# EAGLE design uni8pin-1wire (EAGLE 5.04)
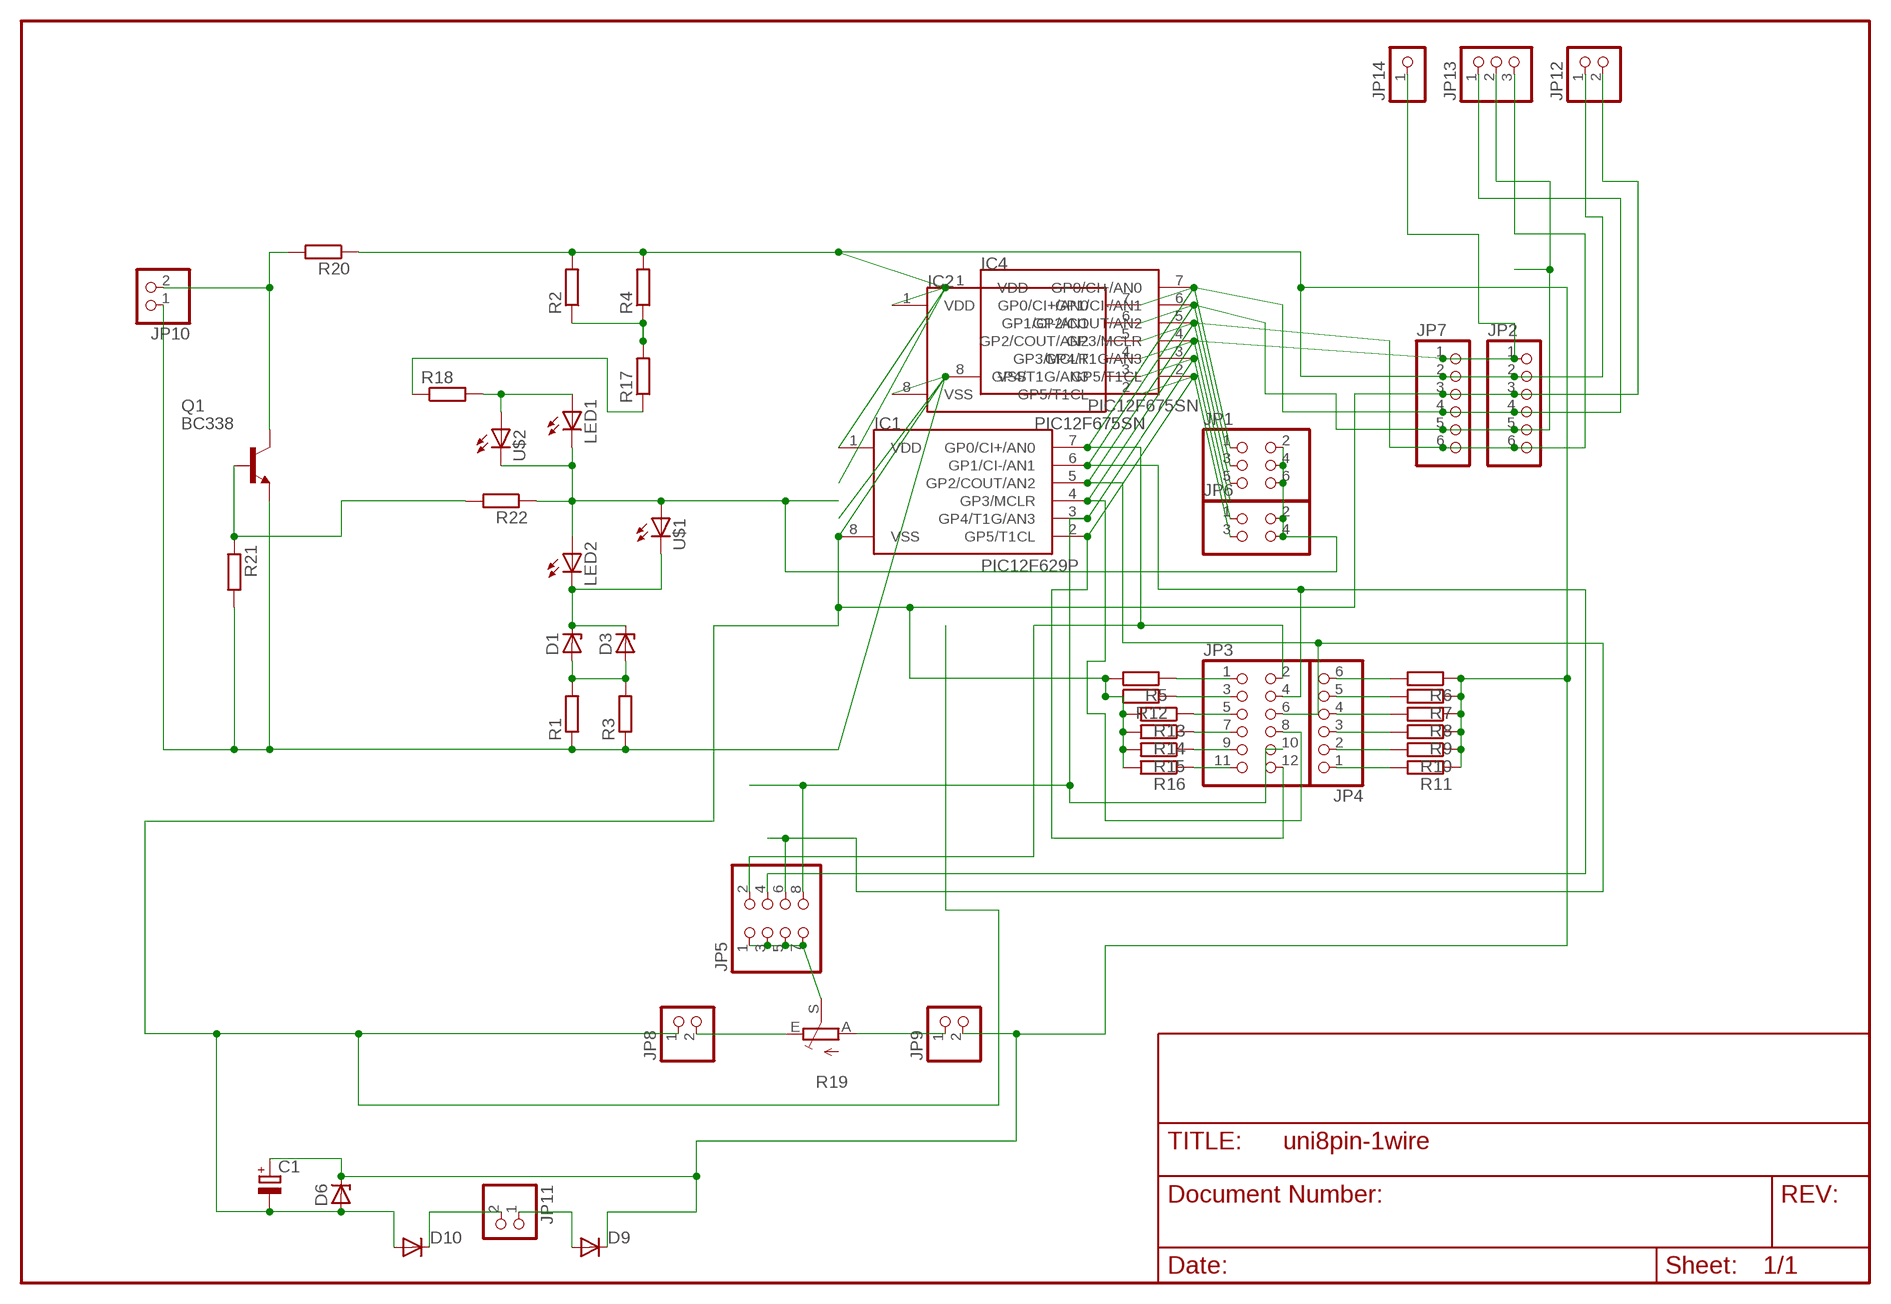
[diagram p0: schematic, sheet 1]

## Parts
C1  CPOL-EU5-13  [2,5-5-FLAT]
D1  ZENER-DIODESOT23  [SOT23]
D3  ZENER-DIODEZD-2.5  [ZDIO-2.5]
D6  ZENER-DIODEZD-2.5  [ZDIO-2.5]
D9  DIODE-D-5  [D-5]
D10  DIODE-D-5  [D-5]
IC1  PIC12F629P  [DIL8]
IC2  PIC12F675SN  [SO-08]
IC4  PIC12F675SN  [SO-08]
JP1  PINHD-2X3  [2X03]
JP2  PINHD-1X6  [1X06]
JP3  PINHD-2X6  [2X06]
JP4  PINHD-1X6  [1X06]
JP5  PINHD-2X4  [2X04]
JP6  PINHD-2X2  [2X02]
JP7  PINHD-1X6  [1X06]
JP8  PINHD-1X2  [1X02]
JP9  PINHD-1X2  [1X02]
JP10  PINHD-1X2  [1X02]
JP11  PINHD-1X2  [1X02]
JP12  PINHD-1X2  [1X02]
JP13  PINHD-1X3  [1X03]
JP14  PINHD-1X1  [1X01]
LED1  LED5MM  [LED5MM]
LED2  LED5MM  [LED5MM]
Q1  BC338  [TO92-EBC]
R1  R-EU_0204/2V  [0204V]
R2  R-EU_0204/2V  [0204V]
R3  R-EU_R1206  [R1206]
R4  R-EU_R1206  [R1206]
R5  R-EU_R1206  [R1206]
R6  R-EU_R1206  [R1206]
R7  R-EU_R1206  [R1206]
R8  R-EU_R1206  [R1206]
R9  R-EU_R1206  [R1206]
R10  R-EU_R1206  [R1206]
R11  R-EU_R1206  [R1206]
R12  R-EU_R1206  [R1206]
R13  R-EU_R1206  [R1206]
R14  R-EU_R1206  [R1206]
R15  R-EU_R1206  [R1206]
R16  R-EU_R1206  [R1206]
R17  R-EU_R0805  [R0805]
R18  R-EU_R0805  [R0805]
R19  TRIM_EU-CA6V  [CA6V]
R20  R-EU_R0805  [R0805]
R21  R-EU_R0805  [R0805]
R22  R-EU_R0805  [R0805]
U$1  LEDCHIPLED_1206  [CHIPLED_1206]
U$2  LEDCHIPLED_1206  [CHIPLED_1206]

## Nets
N$1: IC1.3(GP4/T1G/AN3) IC2.3(GP4/T1G/AN3) IC4.3(GP4/T1G/AN3) JP3.10 JP5.8 JP6.1
N$2: D1.3(C) D3.C LED2.K(C) U$1.C
N$3: D1.1(A) D3.A R1.2 R3.2
N$4: JP1.2 JP1.4 JP1.6 JP6.2 JP6.4 LED1.K(C) LED2.A R22.1 U$1.A U$2.C
N$5: JP10.2 Q1.C R20.2
N$7: R2.1 R4.1 R17.2
N$8: R17.1 R18.1
N$9: IC1.2(GP5/T1CL) IC2.2(GP5/T1CL) IC4.2(GP5/T1CL) JP3.12 JP6.3
N$10: LED1.A R18.2 U$2.A
N$11: IC1.4(GP3/MCLR) IC2.4(GP3/MCLR) IC4.4(GP3/MCLR) JP2.1 JP3.8 JP7.1 JP14.1
N$12: IC1.5(GP2/COUT/AN2) IC2.5(GP2/COUT/AN2) IC4.5(GP2/COUT/AN2) JP1.5 JP2.6 JP3.6 JP5.6 JP7.6 JP13.3
N$13: IC1.6(GP1/CI-/AN1) IC2.6(GP1/CI-/AN1) IC4.6(GP1/CI-/AN1) JP1.3 JP2.5 JP3.4 JP5.4 JP7.5 JP13.2
N$14: IC1.7(GP0/CI+/AN0) IC2.7(GP0/CI+/AN0) IC4.7(GP0/CI+/AN0) JP1.1 JP2.4 JP3.2 JP5.2 JP7.4 JP13.1
N$15: JP4.6 R6.2
N$16: JP5.1 JP5.3 JP5.5 JP5.7 R19.S
N$17: Q1.B R21.1 R22.2
N$18: JP3.1 R5.1
N$21: JP3.3 R12.1
N$22: JP3.5 R13.1
N$23: JP3.7 R14.1
N$24: JP3.9 R15.1
N$25: JP3.11 R16.1
N$26: JP4.5 R7.2
N$27: JP4.4 R8.2
N$28: JP4.3 R9.2
N$29: JP4.2 R10.2
N$30: JP4.1 R11.2
N$31: JP9.1 R19.A
N$32: JP8.2 R19.E
N$34: D10.C JP11.2
N$35: D9.A JP11.1
VDD: C1.+ D6.C D9.C IC1.1(VDD) IC2.1(VDD) IC4.1(VDD) JP2.2 JP7.2 JP9.2 JP12.1 R2.2 R4.2 R6.1 R7.1 R8.1 R9.1 R10.1 R11.1 R20.1
VSS: C1.- D6.A D10.A IC1.8(VSS) IC2.8(VSS) IC4.8(VSS) JP2.3 JP7.3 JP8.1 JP10.1 JP12.2 Q1.E R1.1 R3.1 R5.2 R12.2 R13.2 R14.2 R15.2 R16.2 R21.2

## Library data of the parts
C1 = rcl-2:CPOL-EU: POLARIZED CAPACITOR, European symbol
D1 D3 D6 = diode-1:ZENER-DIODE: Z-Diode
D9 D10 = diode-1:DIODE-: DIODE
IC1 IC2 IC4 = microchip-5:PIC12F6*: uPC nW 1k Program Flash memory 2x Timer Comparator 10b A/D converter/ 4xIN
JP1 = pinhead(2):PINHD-2X3: PIN HEADER
JP2 JP7 = pinhead:PINHD-1X6: PIN HEADER
JP3 = pinhead(2):PINHD-2X6: PIN HEADER
JP4 = pinhead(2):PINHD-1X6: PIN HEADER
JP5 = pinhead(2):PINHD-2X4: PIN HEADER
JP6 = pinhead(2):PINHD-2X2: PIN HEADER
JP8-JP11 = pinhead(2):PINHD-1X2: PIN HEADER
JP12 = pinhead:PINHD-1X2: PIN HEADER
JP13 = pinhead:PINHD-1X3: PIN HEADER
JP14 = pinhead:PINHD-1X1: PIN HEADER
LED1 LED2 = led:LED: LED
Q1 = transistor-npn:BC338*: NPN Transistor
R1-R18 R20-R22 = rcl-2:R-EU_: RESISTOR, European symbol
R19 = pot:TRIM_EU-: POTENTIOMETER
U$1 U$2 = led(2):LED: LED

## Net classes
0 default: width 0.3 mm, drill 0.6 mm, clearance 0.2 mm
1 power: width 0.4 mm, drill 0.6 mm, clearance 0.2 mm

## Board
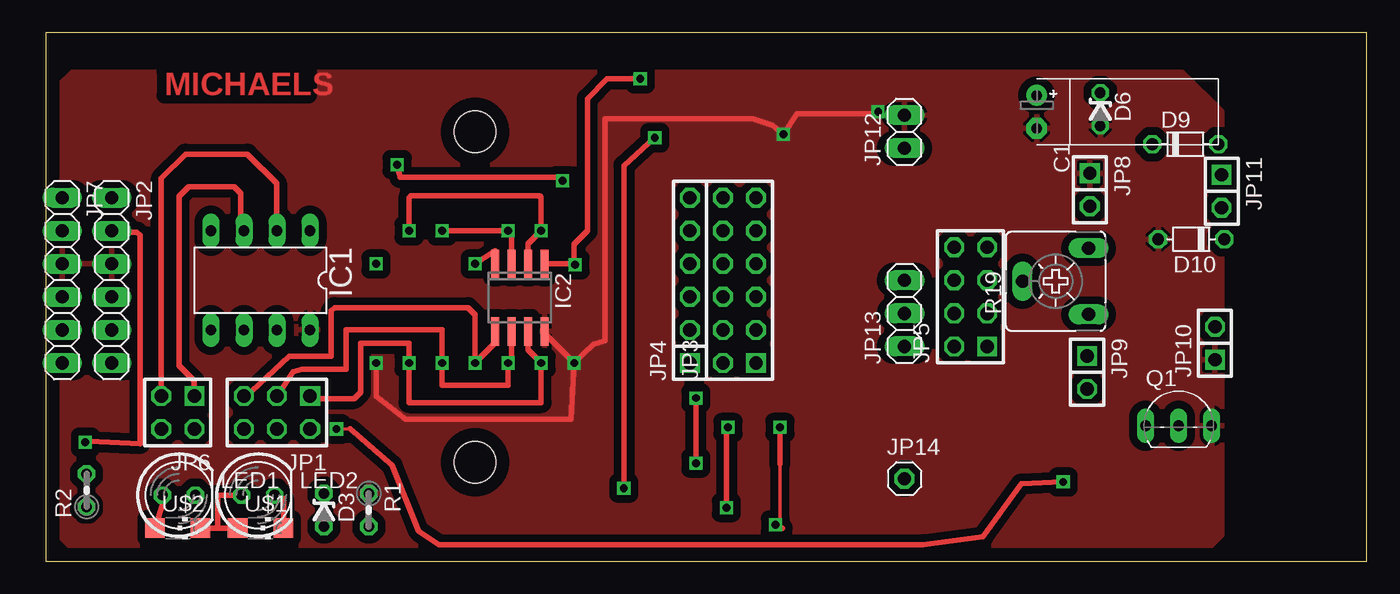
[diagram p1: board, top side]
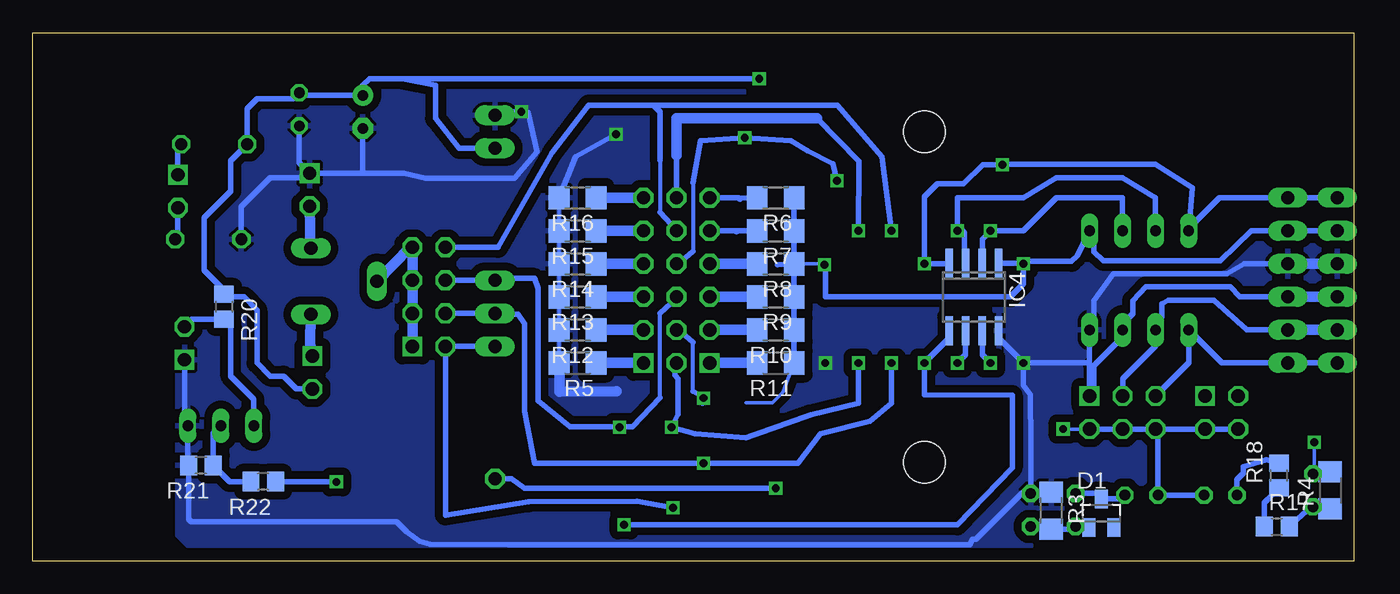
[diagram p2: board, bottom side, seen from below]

Size 101.6 x 40.64 mm. Coordinates in mm from the lower left corner, seen from the top.
Outline: 0,0 101.6,0 101.6,40.64 0,40.64 0,0
Copper layers (1*16): Top 0.035mm / dielectric 1.5mm / Bottom 0.035mm
Design rules "default": minimum track width 10mil, minimum drill 24mil, track to track 8mil, track to pad 8mil, pad to pad 8mil, via to via 8mil, smd to smd 8mil, copper to edge 40mil, drill to drill 8mil, minimum pad ring 10mil, minimum via ring 8mil, stop-mask expansion 4mil, vias tented up to drill 0mil, thermal gap 10mil
Holes 3.2 mm at 33.02,33.02 33.02,7.62

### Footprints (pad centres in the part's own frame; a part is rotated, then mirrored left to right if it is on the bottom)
2,5-5-FLAT = drill 0.813 pad 1.6 round: + -1.27,0 | drill 0.813 pad 1.6 octagon: - 1.27,0
SOT23 = smd 1 x 1.4: 1 -0.95,-1.1; 2 0.95,-1.1; 3 0,1.1
ZDIO-2.5 = drill 0.813 octagon: A 1.27,0; C -1.27,0
D-5 = drill 0.9 octagon: A 2.54,0; C -2.54,0
DIL8 = drill 0.813 long: 1 -3.81,-3.81; 2 -1.27,-3.81; 3 1.27,-3.81; 4 3.81,-3.81; 5 3.81,3.81; 6 1.27,3.81; 7 -1.27,3.81; 8 -3.81,3.81
SO-08 = smd 0.6 x 2.2: 1 -1.905,-2.6; 2 -0.635,-2.6; 3 0.635,-2.6; 4 1.905,-2.6; 5 1.905,2.6; 6 0.635,2.6; 7 -0.635,2.6; 8 -1.905,2.6
2X03 = drill 1.016 square: 1 -2.54,-1.27 | drill 1.016 octagon: 2 -2.54,1.27; 3 0,-1.27; 4 0,1.27; 5 2.54,-1.27; 6 2.54,1.27
1X06 = drill 1.016 long: 1 -6.35,0; 2 -3.81,0; 3 -1.27,0; 4 1.27,0; 5 3.81,0; 6 6.35,0
2X06 = drill 1.016 square: 1 -6.35,-1.27 | drill 1.016 octagon: 2 -6.35,1.27; 3 -3.81,-1.27; 4 -3.81,1.27; 5 -1.27,-1.27; 6 -1.27,1.27; 7 1.27,-1.27; 8 1.27,1.27; 9 3.81,-1.27; 10 3.81,1.27; 11 6.35,-1.27; 12 6.35,1.27
1X06' = drill 1.016 square: 1 -6.35,0 | drill 1.016 octagon: 2 -3.81,0; 3 -1.27,0; 4 1.27,0; 5 3.81,0; 6 6.35,0
2X04 = drill 1.016 square: 1 -3.81,-1.27 | drill 1.016 octagon: 2 -3.81,1.27; 3 -1.27,-1.27; 4 -1.27,1.27; 5 1.27,-1.27; 6 1.27,1.27; 7 3.81,-1.27; 8 3.81,1.27
2X02 = drill 1.016 square: 1 -1.27,-1.27 | drill 1.016 octagon: 2 -1.27,1.27; 3 1.27,-1.27; 4 1.27,1.27
1X02 = drill 1.016 square: 1 -1.27,0 | drill 1.016 octagon: 2 1.27,0
1X02' = drill 1.016 long: 1 -1.27,0; 2 1.27,0
1X03 = drill 1.016 long: 1 -2.54,0; 2 0,0; 3 2.54,0
1X01 = drill 1.016 octagon: 1 0,0
LED5MM = drill 0.813 octagon: A -1.27,0; K 1.27,0
TO92-EBC = drill 0.813 long: B 0,-1.27; C -2.54,-1.27; E 2.54,-1.27
0204V = drill 0.813 octagon: 1 -1.27,0; 2 1.27,0
R1206 = smd 1.6 x 1.803: 1 -1.422,0; 2 1.422,0
R0805 = smd 1.3 x 1.5: 1 -0.95,0; 2 0.95,0
CA6V = drill 1.016 long: A -2.54,-2.54; E 2.54,-2.54; S 0,2.54
CHIPLED_1206 = smd 1.5 x 1.5: A 0,-1.75; C 0,1.75

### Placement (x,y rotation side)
C1  76.2,34.54 270 top
D1  19.4,3.69 0 bottom
D3  21.39,3.94 270 top
D6  81.09,34.74 270 top
D9  87.63,32.06 0 top
D10  88.09,24.75 180 top
IC1  16.51,21.59 180 top
IC2  36.46,20.26 180 top
IC4  29.21,20.32 180 bottom
JP1  17.78,11.43 180 top
JP2  5.08,21.59 270 top
JP3  53.34,21.59 90 top
JP4  [1X06']  49.53,21.59 90 top
JP5  71.12,20.32 90 top
JP6  10.16,11.43 180 top
JP7  1.27,21.59 270 top
JP8  80.3,28.56 270 top
JP9  80.08,14.51 270 top
JP10  89.92,16.76 90 top
JP11  90.42,28.45 270 top
JP12  [1X02']  66.04,33.02 90 top
JP13  66.04,19.05 90 top
JP14  66.04,6.35 0 top
LED1  10.24,5.08 0 top
LED2  16.33,5.08 0 top
Q1  87.12,11.68 0 top
R1  24.85,3.94 270 top
R2  3.14,5.45 90 top
R3  23.27,3.89 270 bottom
R4  1.81,5.46 90 bottom
R5  59.69,15.24 180 bottom
R6  44.45,27.94 180 bottom
R7  44.45,25.4 180 bottom
R8  44.45,22.86 180 bottom
R9  44.45,20.32 180 bottom
R10  44.45,17.78 180 bottom
R11  44.45,15.24 180 bottom
R12  59.69,17.78 180 bottom
R13  59.69,20.32 180 bottom
R14  59.69,22.86 180 bottom
R15  59.69,25.4 180 bottom
R16  59.69,27.94 180 bottom
R17  5.92,2.66 0 bottom
R18  5.75,6.59 90 bottom
R19  77.66,21.52 90 top
R20  86.87,19.56 270 bottom
R21  88.65,7.37 180 bottom
R22  83.86,6.11 180 bottom
U$1  16.51,2.54 270 top
U$2  10.16,2.54 270 top

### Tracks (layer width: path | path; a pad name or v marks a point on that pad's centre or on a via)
N$1  (via drill 0.6)
  Top 0.406: JP6.1 11.43,13.86 10.25,15.04 10.25,28.04 11,28.79 14.5,28.79 15,28.29 15,25.79 14.97,25.82 IC1.3 | IC2.3 35.83,25.14 v35.56,25.4 v30.48,25.4
  Bottom 0.305: 53.34,30.83 53.34,26.83
  Bottom 0.406: JP3.10 52.07,25.44 53.34,26.83 | v35.56,25.4 36.27,31.1 39.71,35.05 53.85,35.05 | IC1.3 15.24,27.94 17.78,29.46 22.86,29.46 25.4,27.94 30.48,27.94 v30.48,25.4 30.11,25.4 29.96,25.25 29.96,23.04 IC4.3 | JP5.8 65.81,24.13 61.64,31.41 58.84,35.05 53.85,35.05 | 53.34,30.83 53.34,34.54 53.85,35.05
N$2
  Top 0.406: U$1.C 18.29,2.54 18.29,4.79 17.6,4.79 LED2.K
  Bottom 0.406: D3.C 19.82,5.21 D1.3 17.9,4.79 LED2.K
N$3
  Bottom 0.406: R1.2 23.47,2.67 R3.2 21.6,2.46 D3.A 20.43,2.67 D1.1
N$4  (via drill 0.6)
  Top 0.254: v22.35,10.16 23.4,10.17
  Top 0.406: 23.4,10.17 26.65,7.37 28.68,2.31 30.23,1.27 67.46,1.27 72.08,1.87 75.02,5.94 v78.23,6.1 | U$2.C U$1.A 13.21,2.54 13.21,5.08 LED2.A
  Bottom 0.254: JP1.2 v22.35,10.16
  Bottom 0.406: R22.1 81.29,6.11 v78.23,6.1 | JP1.6 15.06,9.98 LED2.A LED1.K | JP1.6 JP1.4 JP1.2 | JP6.4 JP6.2 JP1.6
N$5
  Bottom 0.406: Q1.C 84.58,12.45 86.36,14.22 86.36,18.1 R20.2 89.34,18.61 JP10.2
N$7
  Bottom 0.406: R17.2 3.89,3.66 R2.1 3.06,3.93 R4.1
N$8
  Bottom 0.406: R18.1 6.62,4.75 6.87,4.5 R17.1
N$9  (via drill 0.6)
  Top 0.406: IC2.2 37.09,24.39 v38.1,25.4 38.1,27.94 | JP6.3 8.89,29.43 10.75,31.29 15.5,31.29 17.75,29.04 17.75,26.54 18,26.29 17.51,25.8 | 17.51,25.8 17.5,25.79 | 17.51,25.8 IC1.2 | 38.04,28.04 38.1,27.98 38.1,27.94 | v27.94,25.4 27.94,27.94 28.08,28.08 37.95,28.08 38.08,27.94 38.1,27.94
  Bottom 0.406: v38.1,25.4 38.06,30.73 41.27,34.04 | 52.07,31.22 JP3.12 | IC4.2 28.57,24.77 v27.94,25.4 25.4,25.4 22.86,27.94 17.78,27.94 IC1.2
  Bottom 0.813: 41.27,34.04 52.07,34.04 52.07,31.22
N$10
  Top 0.406: LED1.A 9.17,5.08 U$2.A
  Bottom 0.406: R18.2 6.71,7.79 8.5,7.25 8.5,6.75 9,6.25 9,5.11 LED1.A
N$11  (via drill 0.6)
  Top 0.406: IC2.4 34.55,23.86 v33.02,22.86 | v44.45,5.62 44.45,30.41 v46.83,32.55 | v39.75,29.25 39.25,29.5 27.25,29.5 v27.02,30.48
  Bottom 0.305: 50.8,29.08 50.8,23.83
  Bottom 0.406: 12.43,25.86 12.5,25.79 | 12.43,25.86 IC1.4 12.43,28.72 15.25,30.52 26.73,30.52 26.77,30.48 v27.02,30.48 28.52,30.48 30,29 32,29 33,28 33,22.88 v33.02,22.86 31.18,22.86 IC4.4 | 12.43,25.86 10.35,27.94 JP2.1 JP7.1 | JP3.8 51.93,22.86 50.8,23.83 | JP14.1 64.77,6.35 63.75,5.62 v44.45,5.62 | v39.75,29.25 40.04,30.54 42,31.56 43.27,32.32 v46.83,32.55 50.25,32.33 50.8,29.08
N$12  (via drill 0.6)
  Top 0.254: 56.46,7.48 56.46,2.7 56.58,2.54
  Top 0.406: IC2.5 34.55,16.77 v33.02,15.24 | 33.04,15.04 33.02,15.06 v33.02,15.24 | 56.58,2.54 56.63,2.54 v56.11,2.79 | v33.02,15.24 33.02,18.94 32.46,19.5 22.21,19.5 21.96,19.25 21.96,15.75 18.71,15.75 15.25,12.54 15.24,12.54 JP1.5 | 56.46,7.48 v56.46,10.29
  Bottom 0.305: 53.34,12.58 53.34,19.08
  Bottom 0.406: 56.42,10.33 60.25,10.33 62.74,12.33 62.74,21 63,21.75 65.88,21.75 JP13.3 JP5.6 | 53.34,12.58 55.46,10.33 56.42,10.33 | v56.11,2.79 30.48,2.79 26.26,7.2 26.26,12.75 33.02,12.79 v33.02,15.24 31.11,17.14 IC4.5 | JP3.6 52.07,20.22 53.34,19.08 | JP7.6 JP2.6 10.16,15.24 IC1.5 12.7,15.24 JP1.5 | v56.46,10.29 56.42,10.33
N$13  (via drill 0.6)
  Top 0.406: IC2.6 35.83,15.51 v35.56,15.24 35.59,15.24 35.79,15.04 35.54,14.79 35.54,13.54 30.48,13.54 v30.48,15.24 30.48,17.78 23.11,17.78 23.11,14.74 19.7,14.74 19.03,14.57 JP1.3 | v50,7.54 v50,12.54
  Bottom 0.305: 50.8,13.08 50.8,16.83
  Bottom 0.406: JP2.5 8.24,17.78 10.75,20.07 14.25,20.07 14.75,19.79 14.75,18.79 15.13,18.41 | 15.13,18.41 15.25,18.29 15.25,16.54 17.75,14.04 17.75,12.54 17.78,12.57 JP1.3 | 15.13,18.41 IC1.6 | 52.07,17.44 JP3.4 52.01,17.78 51.96,17.83 50.8,16.83 | IC4.6 29.84,15.88 v30.48,15.24 | 50.8,13.08 50.05,12.63 50.09,12.13 v50,12.54 | 35.83,15.51 v35.56,15.24 35.56,12.16 37.22,10.75 41,9.79 42.75,7.54 v50,7.54 63,7.54 63.75,11.54 63.75,18.25 64.25,19 65.99,19 JP13.2 | JP13.2 JP5.4 | 64.75,19.25 65.84,19.25 JP13.2
  Bottom 0.813: JP7.5 JP2.5
N$14  (via drill 0.6)
  Top 0.406: IC2.7 37.09,16.25 v38.1,15.24 v38.1,15.23 38.29,15.04 38.1,14.85 | 38.1,14.85 38.04,14.79 | 38.1,14.85 38.1,12.2 27.94,12.2 v27.94,15.24 27.94,16.73 27.96,16.75 24.21,16.75 24.21,13 23.71,12.5 20.52,12.5 JP1.1 | v52.34,4.12 52.34,9.7 52.3,10.45 v52.46,10.29
  Bottom 0.406: JP2.4 8.78,20.32 9.5,21.08 16,21.08 17,20.04 17,19.04 17.51,18.53 IC1.7 17.51,17.53 20,15.04 20,13.04 20.32,12.72 JP1.1 | IC4.7 28.57,15.88 v27.94,15.24 | v52.34,4.12 55.13,4.6 63.46,4.56 69.84,3.55 69.85,3.56 JP5.2 JP13.1 | 52.21,15.1 52.21,14.29 51.96,14.04 51.96,11.29 v52.46,10.29 50.67,9.79 46.75,9.5 41.75,11.25 38.1,12.15 v38.1,15.24
  Bottom 0.813: JP7.4 JP2.4 | 52.21,15.1 JP3.2
N$15
  Bottom 0.406: R6.2 47.14,27.9 47.21,27.83 47.32,27.94 JP4.6
N$16
  Bottom 0.813: R19.S 72.58,24.13 JP5.7 JP5.5 JP5.3 JP5.1
N$17
  Bottom 0.406: Q1.B 87.7,9.84 R21.1 86.44,6.11 R22.2
N$18
  Bottom 0.813: JP3.1 R5.1
N$21
  Bottom 0.813: JP3.3 R12.1
N$22
  Bottom 0.813: JP3.5 R13.1
N$23
  Bottom 0.813: JP3.7 R14.1
N$24
  Bottom 0.813: JP3.9 R15.1
N$25
  Bottom 0.813: JP3.11 R16.1
N$26
  Bottom 0.406: R7.2 47.39,25.4 47.46,25.33 47.53,25.4 JP4.5
N$27
  Bottom 0.813: R8.2 JP4.4
N$28
  Bottom 0.813: R9.2 JP4.3
N$29
  Bottom 0.813: R10.2 JP4.2
N$30
  Bottom 0.813: R11.2 JP4.1
N$31
  Bottom 0.813: JP9.1 80.24,16.69 R19.A
N$32
  Bottom 0.813: JP8.2 80.26,25.56 R19.E
N$34
  Bottom 0.406: JP11.2 90.42,24.95 D10.C
N$35
  Bottom 0.406: JP11.1 90.42,31.8 D9.A
VDD  (via drill 0.6)
  Top 0.254: 3.36,9.21 3.12,9.21 v3.05,9.14
  Top 0.406: 38.37,23.12 IC2.1 40.71,22.86 v40.71,22.79 40.64,22.86 40.64,24.38 41.66,25.4 41.66,35.56 43.18,37.08 v45.72,37.08 | 3.36,9.21 7.25,9.04 7.25,25.04 7,25.29 5,25.29 | 5,25.29 4.75,25.29 4.5,25.54 4.75,25.54 5,25.29 | 5,25.29 5.08,25.37 JP2.2
  Bottom 0.254: R8.1 40.78,22.86 v40.71,22.79 | v3.05,9.14 3.05,6.81 R2.2 | R11.1 43.9,13 44.7,12.19 46.74,12.19
  Bottom 0.406: JP7.2 JP2.2 7.89,25.4 10.25,23.11 19.25,23.11 20,23.79 20,25.54 20.25,25.79 20.05,25.99 IC1.1 21.26,23.49 21.71,23.04 25.4,23.04 v25.4,22.86 | IC4.1 25.46,22.92 v25.4,22.86 | JP12.1 68.79,31.73 70.61,34.04 70.61,36.58 73.15,37.08 | R2.2 1.97,6.72 R4.2 | R8.1 44.3,22.79 | JP9.2 81.31,13.24 82.3,14.22 83.31,14.22 84.33,15.24 84.33,19.3 85.34,20.32 86.68,20.32 R20.1 86.87,20.83 88.39,22.35 88.39,26.42 86.36,28.45 86.36,30.79 D9.C 85.09,34.8 84.33,35.56 81.54,35.56 D6.C 80.9,35.81 C1.+ 76.2,36.58 75.69,37.08 73.15,37.08 | v45.72,37.08 73.15,37.08 | v25.4,22.86 25.4,21.34 26.42,20.32 40.64,20.32 40.64,22.72 v40.71,22.79 | R11.1 R10.1 R9.1 R8.1 | R8.1 R7.1 R6.1
VSS  (via drill 0.6)
  Top 0.406: IC2.8 38.37,17.52 v40.64,15.24 | v40.64,15.24 42.14,16.69 43,16.94 43,34 54.39,34 55.88,33.53 v56.72,32.81 57.78,34.41 64.01,34.41 v64.01,34.54 | v25.4,15.24 25.4,12.7 27.69,10.91 40.39,10.91 v40.64,15.24
  Bottom 0.254: R5.2 R12.2 R13.2 R14.2 R15.2 R16.2
  Bottom 0.406: JP2.3 8.43,22.86 9.75,22.1 18.5,22.1 20,20.04 20,18.1 IC1.8 20.32,15.24 | 40.54,15.29 40.59,15.24 v40.64,15.24 | R16.2 59.84,31.09 v56.72,32.81 | IC4.8 27.3,17.14 v25.4,15.24 | 20.32,15.24 20.32,13.1 | 20.32,15.24 v25.4,15.24 | v25.4,15.24 25.4,13.54 24.88,12.79 24.85,8.98 R1.1 | 76.2,29.83 73.01,29.83 71.37,29.44 64.54,29.44 62.8,31.47 63.5,34.5 66.04,34.5 JP12.2 66.04,34.54 v64.01,34.54 | 76.2,29.83 JP8.1 | R1.1 24.89,5.25 25.5,5.25 29.07,1.68 29.32,1.68 29.5,1.27 65,1.27 71.04,1.29 71.85,1.54 72.84,2.28 73.61,3.05 89.41,3.05 89.6,3.24 R21.2 89.66,7.43 Q1.E 89.92,10.67 JP10.1 | R1.1 23.37,5.21 R3.1 | D10.A 85.55,27.23 83.31,29.46 80.67,29.46 JP8.1 | D6.A 81.09,30.62 JP8.1 | 76.2,29.83 C1.-
  Bottom 0.813: JP7.3 JP2.3 | R5.2 61.08,15.19 61.08,13.03 56.71,13.08
  pour Bottom (isolate 0.61, rank 5): 1.02,36.58 1.02,2.03 3.05,0 88.39,0 90.42,2.03 90.42,34.54 87.38,37.59 2.03,37.59
  pour Top (isolate 0.61, rank 5): 1.02,36.58 1.02,2.03 3.05,0 88.39,0 90.42,2.03 90.42,34.54 87.38,37.59 2.03,37.59

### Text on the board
Top: MICHAELS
